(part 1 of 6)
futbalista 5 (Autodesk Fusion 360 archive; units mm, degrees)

design "futbalista 5" references "light sensor", "stlpik", "Raspberry Pi 4 Model B", "arduino nano strong", "futbalista 4", "18650 battery variations", "BTS7960 43A HIGH POWER H BRIDGE MODULE", "cam v2.1 rpi", "Solenoid JF-0826B"
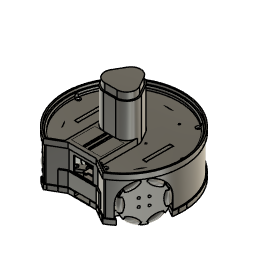
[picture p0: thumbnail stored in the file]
component_insert "Component Insert1"
step "00000000-0000-0000-0000-000000000000" TotalAngle 360
component_insert "Component Insert2"
component_insert "Component Insert3"
component_insert "Component Insert4"
component_insert "Component Insert5"
component_insert "Component Insert6"
component_insert "Component Insert7"
position "Position1"
component_insert "Component Insert8"
position "Position2"
component_insert "Component Insert9"
position "Position3"
sketch "Sketch1" plane through (0, 0, 0) normal (0, 0, 1) x axis (1, 0, 0)
  circle C1 centre (0, 0) radius 90
  circle C2 centre (0, 0) radius 86.5
  point P1 (0, 0)
  point P2 (0, 0)
  point P3 (0, 0)
  coincident P1 P2
  coincident P1 P3
component_insert "Component Insert11"
sketch "Sketch2" plane through (0, 0, -20.25) normal (0, 0, -1) x axis (1, 0, 0)
  line L1 (48.0762, -50.4536) -> (13.4352, -30.4536)
  line L2 (68.0762, -15.8125) -> (48.0762, -50.4536)
  line L3 (33.4352, 4.1875) -> (68.0762, -15.8125)
  line L4 (13.4352, -30.4536) -> (33.4352, 4.1875)
  line L5 (74.5, -6) -> (74.5, 6)
  line L6 (79.5, -6) -> (74.5, -6)
  line L7 (79.5, 6) -> (79.5, -6)
  line L8 (74.5, 6) -> (79.5, 6)
  circle C1 centre (46.9782, -46.3555) radius 1.5
  circle C2 centre (17.5333, -29.3555) radius 1.5
  circle C3 centre (34.5333, 0.0894) radius 1.5
  circle C4 centre (63.9782, -16.9106) radius 1.5
  circle C5 centre (77, 1) radius 1
position "Position8"
mirror_component "MirrorComponent1"
derived_instance "DerivedInstance1"
step "00000000-0000-0000-0000-000000000000" TotalAngle 360
component_insert "Component Insert12"
position "Position5"
position "Position9"
sketch "Sketch3" plane through (0, 0, -20.25) normal (0, 0, -1) x axis (1, 0, 0)
  line L1 (-71.6074, -10.2238) -> (-73.1099, -12.8262)
  line L2 (-73.1099, -7.1738) -> (-71.6074, -9.7762)
  line L3 (-76.5025, -6.95) -> (-73.4975, -6.95)
  line L4 (-78.3926, -9.7762) -> (-76.8901, -7.1738)
  line L5 (-76.8901, -12.8262) -> (-78.3926, -10.2238)
  line L6 (-73.4975, -13.05) -> (-76.5025, -13.05)
  arc A1 centre (-75, -10) radius 3.4 clockwise from (-71.6074, -9.7762) to (-71.6074, -10.2238)
  arc A2 centre (-75, -10) radius 3.4 clockwise from (-73.4975, -6.95) to (-73.1099, -7.1738)
  arc A3 centre (-75, -10) radius 3.4 clockwise from (-76.8901, -7.1738) to (-76.5025, -6.95)
  arc A4 centre (-75, -10) radius 3.4 clockwise from (-78.3926, -10.2238) to (-78.3926, -9.7762)
  arc A5 centre (-75, -10) radius 3.4 clockwise from (-76.5025, -13.05) to (-76.8901, -12.8262)
  arc A6 centre (-75, -10) radius 3.4 clockwise from (-73.1099, -12.8262) to (-73.4975, -13.05)
position "Position10"
mirror_component "MirrorComponent2"
derived_instance "DerivedInstance2"
step "00000000-0000-0000-0000-000000000000" TotalAngle 360
position "Position6"
position "Position7"
sketch "Sketch5" plane through (0, 0, -20.25) normal (0, 0, -1) x axis (1, 0, 0)
  line L1 (-18.5675, 22.4402) -> (-28.7175, 4.8598)
  line L2 (-43.0483, 40.0382) -> (-19.6656, 26.5382)
  line L3 (-56.1983, 17.2618) -> (-43.0483, 40.0382)
  line L4 (-32.8156, 3.7618) -> (-56.1983, 17.2618)
  line L5 (52.4064, -52.9536) -> (17.7653, -32.9536)
  line L6 (72.4064, -18.3125) -> (52.4064, -52.9536)
  line L7 (37.7653, 1.6875) -> (72.4064, -18.3125)
  line L8 (17.7653, -32.9536) -> (37.7653, 1.6875)
  line L9 (51.0414, -29.4688) -> (-36.6762, 21.175)
  line L10 (62.2343, -35.931) -> (51.0414, -29.4688)
  line L11 (26.9496, 67.1257) -> (25.4471, 69.7281)
  line L12 (30.3422, 66.9019) -> (27.3372, 66.9019)
  line L13 (32.2324, 69.7281) -> (30.7299, 67.1257)
  line L14 (30.7299, 72.7781) -> (32.2324, 70.1757)
  line L15 (27.3372, 73.0019) -> (30.3422, 73.0019)
  line L16 (25.4471, 70.1757) -> (26.9496, 72.7781)
  line L17 (-25.4471, 69.7281) -> (-26.9496, 67.1257)
  line L18 (-26.9496, 72.7781) -> (-25.4471, 70.1757)
  line L19 (-30.3422, 73.0019) -> (-27.3372, 73.0019)
  line L20 (-32.2324, 70.1757) -> (-30.7299, 72.7781)
  line L21 (-30.7299, 67.1257) -> (-32.2324, 69.7281)
  line L22 (-27.3372, 66.9019) -> (-30.3422, 66.9019)
  line L23 (28.8397, 69.9519) -> (-28.8397, 69.9519)
  line L24 (0, 0) -> (0, 69.9519)
  arc A1 centre (-31.3156, 6.3598) radius 3 clockwise from (-28.7175, 4.8598) to (-32.8156, 3.7618)
  arc A2 centre (-21.1656, 23.9402) radius 3 clockwise from (-19.6656, 26.5382) to (-18.5675, 22.4402)
  circle C1 centre (-34.6756, 10.8401) radius 1.7
  circle C2 centre (-36.6762, 21.175) radius 4.95
  circle C3 centre (-26.7256, 24.6099) radius 1.7
  circle C4 centre (-38.6768, 31.5099) radius 1.7
  circle C5 centre (-46.6268, 17.7401) radius 1.7
  circle C6 centre (51.3083, -48.8555) radius 1.5
  circle C7 centre (21.8634, -31.8555) radius 1.5
  circle C8 centre (38.8634, -2.4106) radius 1.5
  circle C9 centre (68.3083, -19.4106) radius 1.5
  arc A3 centre (28.8397, 69.9519) radius 3.4 clockwise from (27.3372, 66.9019) to (26.9496, 67.1257)
  arc A4 centre (28.8397, 69.9519) radius 3.4 clockwise from (30.7299, 67.1257) to (30.3422, 66.9019)
  arc A5 centre (28.8397, 69.9519) radius 3.4 clockwise from (32.2324, 70.1757) to (32.2324, 69.7281)
  arc A6 centre (28.8397, 69.9519) radius 3.4 clockwise from (30.3422, 73.0019) to (30.7299, 72.7781)
  arc A7 centre (28.8397, 69.9519) radius 3.4 clockwise from (26.9496, 72.7781) to (27.3372, 73.0019)
  arc A8 centre (28.8397, 69.9519) radius 3.4 clockwise from (25.4471, 69.7281) to (25.4471, 70.1757)
  arc A9 centre (-28.8397, 69.9519) radius 3.4 clockwise from (-25.4471, 70.1757) to (-25.4471, 69.7281)
  arc A10 centre (-28.8397, 69.9519) radius 3.4 clockwise from (-27.3372, 73.0019) to (-26.9496, 72.7781)
  arc A11 centre (-28.8397, 69.9519) radius 3.4 clockwise from (-30.7299, 72.7781) to (-30.3422, 73.0019)
  arc A12 centre (-28.8397, 69.9519) radius 3.4 clockwise from (-32.2324, 69.7281) to (-32.2324, 70.1757)
  arc A13 centre (-28.8397, 69.9519) radius 3.4 clockwise from (-30.3422, 66.9019) to (-30.7299, 67.1257)
  arc A14 centre (-28.8397, 69.9519) radius 3.4 clockwise from (-26.9496, 67.1257) to (-27.3372, 66.9019)
  point P11 (-36.6762, 21.175)
  point P23 (-36.6762, 21.175)
  point P25 (62.2343, -35.931)
  point P42 (-28.8397, 69.9519)
  point P52 (-28.8397, 69.9519)
  point P29 (28.8397, 69.9519)
  point P53 (28.8397, 69.9519)
  point P54 (0, 69.9519)
  point P1 (0, 0)
  point P55 (0, 0)
  coincident P11 P23
  perpendicular L8 L9
  coincident L6 P25
  perpendicular L6 L10
  coincident P42 P52
  coincident P29 P53
  midpoint L23 P54
  coincident P1 P55
position "Position11"
position "Position12"
position "Position13"
position "Position20"
position "Position22"
sketch "Sketch4" plane through (0, 0, -20.25) normal (0, 0, -1) x axis (1, 0, 0)
  line L1 (52.2343, -53.2515) -> (17.5933, -33.2515)
  line L2 (72.2343, -18.6105) -> (52.2343, -53.2515)
  line L3 (37.5933, 1.3895) -> (72.2343, -18.6105)
  line L4 (17.5933, -33.2515) -> (37.5933, 1.3895)
  line L5 (28.7175, 4.8598) -> (18.5675, 22.4402)
  line L6 (56.1983, 17.2618) -> (32.8156, 3.7618)
  line L7 (43.0483, 40.0382) -> (56.1983, 17.2618)
  line L8 (19.6656, 26.5382) -> (43.0483, 40.0382)
  line L9 (45.6463, 41.5382) -> (43.0483, 40.0382)
  line L10 (56.1983, 17.2618) -> (43.0483, 40.0382)
  line L11 (56.1983, 17.2618) -> (58.7963, 18.7618)
  line L12 (45.6463, 41.5382) -> (58.7963, 18.7618)
  line L13 (-18.5675, 22.4402) -> (-28.7175, 4.8598)
  line L14 (-43.0483, 40.0382) -> (-19.6656, 26.5382)
  line L15 (-56.1983, 17.2618) -> (-43.0483, 40.0382)
  line L16 (-32.8156, 3.7618) -> (-56.1983, 17.2618)
  line L17 (-58.7963, 18.7618) -> (-56.1983, 17.2618)
  line L18 (-43.0483, 40.0382) -> (-56.1983, 17.2618)
  line L19 (-43.0483, 40.0382) -> (-45.6463, 41.5382)
  line L20 (-58.7963, 18.7618) -> (-45.6463, 41.5382)
  line L21 (-10.15, -27.3) -> (10.15, -27.3)
  line L22 (-13.15, -57.3) -> (-13.15, -30.3)
  line L23 (13.15, -57.3) -> (-13.15, -57.3)
  line L24 (13.15, -30.3) -> (13.15, -57.3)
  line L25 (13.15, -60.3) -> (13.15, -57.3)
  line L26 (-13.15, -57.3) -> (13.15, -57.3)
  line L27 (-13.15, -57.3) -> (-13.15, -60.3)
  line L28 (13.15, -60.3) -> (-13.15, -60.3)
  line L29 (-42.4462, -61.5189) -> (-32.0538, -67.5189)
  line L30 (-44.9462, -65.849) -> (-42.4462, -61.5189)
  line L31 (-34.5538, -71.849) -> (-44.9462, -65.849)
  line L32 (-32.0538, -67.5189) -> (-34.5538, -71.849)
  line L33 (32.0538, -67.5189) -> (42.4462, -61.5189)
  line L34 (34.5538, -71.849) -> (32.0538, -67.5189)
  line L35 (44.9462, -65.849) -> (34.5538, -71.849)
  line L36 (42.4462, -61.5189) -> (44.9462, -65.849)
  line L37 (44.6578, -56.9019) -> (47.6628, -56.9019)
  line L38 (42.7676, -59.7281) -> (44.2701, -57.1257)
  line L39 (44.2701, -62.7781) -> (42.7676, -60.1757)
  line L40 (47.6628, -63.0019) -> (44.6578, -63.0019)
  line L41 (49.5529, -60.1757) -> (48.0504, -62.7781)
  line L42 (48.0504, -57.1257) -> (49.5529, -59.7281)
  line L43 (-47.6628, -56.9019) -> (-44.6578, -56.9019)
  line L44 (-49.5529, -59.7281) -> (-48.0504, -57.1257)
  line L45 (-48.0504, -62.7781) -> (-49.5529, -60.1757)
  line L46 (-44.6578, -63.0019) -> (-47.6628, -63.0019)
  line L47 (-42.7676, -60.1757) -> (-44.2701, -62.7781)
  line L48 (-44.2701, -57.1257) -> (-42.7676, -59.7281)
  line L49 (-71.6074, -10.2238) -> (-73.1099, -12.8262)
  line L50 (-73.1099, -7.1738) -> (-71.6074, -9.7762)
  line L51 (-76.5025, -6.95) -> (-73.4975, -6.95)
  line L52 (-78.3926, -9.7762) -> (-76.8901, -7.1738)
  line L53 (-76.8901, -12.8262) -> (-78.3926, -10.2238)
  line L54 (-73.4975, -13.05) -> (-76.5025, -13.05)
  line L55 (-74.5, 6) -> (-74.5, -6)
  line L56 (-79.5, 6) -> (-74.5, 6)
  line L57 (-79.5, -6) -> (-79.5, 6)
  line L58 (-74.5, -6) -> (-79.5, -6)
  line L59 (32.0538, 42.3849) -> (42.4462, 48.3849)
  line L60 (34.5538, 38.0548) -> (32.0538, 42.3849)
  line L61 (44.9462, 44.0548) -> (34.5538, 38.0548)
  line L62 (42.4462, 48.3849) -> (44.9462, 44.0548)
  line L63 (25.4471, 40.1757) -> (26.9496, 42.7781)
  line L64 (26.9496, 37.1257) -> (25.4471, 39.7281)
  line L65 (30.3422, 36.9019) -> (27.3372, 36.9019)
  line L66 (32.2324, 39.7281) -> (30.7299, 37.1257)
  line L67 (30.7299, 42.7781) -> (32.2324, 40.1757)
  line L68 (27.3372, 43.0019) -> (30.3422, 43.0019)
  line L69 (-26.9496, 42.7781) -> (-25.4471, 40.1757)
  line L70 (-30.3422, 43.0019) -> (-27.3372, 43.0019)
  line L71 (-32.2324, 40.1757) -> (-30.7299, 42.7781)
  line L72 (-30.7299, 37.1257) -> (-32.2324, 39.7281)
  line L73 (-27.3372, 36.9019) -> (-30.3422, 36.9019)
  line L74 (-25.4471, 39.7281) -> (-26.9496, 37.1257)
  line L75 (-42.4462, 48.3849) -> (-32.0538, 42.3849)
  line L76 (-44.9462, 44.0548) -> (-42.4462, 48.3849)
  line L77 (-34.5538, 38.0548) -> (-44.9462, 44.0548)
  line L78 (-32.0538, 42.3849) -> (-34.5538, 38.0548)
  line L79 (74.5, -6) -> (74.5, 6)
  line L80 (79.5, -6) -> (74.5, -6)
  line L81 (79.5, 6) -> (79.5, -6)
  line L82 (74.5, 6) -> (79.5, 6)
  line L83 (73.1099, -12.8262) -> (71.6074, -10.2238)
  line L84 (76.5025, -13.05) -> (73.4975, -13.05)
  line L85 (78.3926, -10.2238) -> (76.8901, -12.8262)
  line L86 (76.8901, -7.1738) -> (78.3926, -9.7762)
  line L87 (73.4975, -6.95) -> (76.5025, -6.95)
  line L88 (71.6074, -9.7762) -> (73.1099, -7.1738)
  line L89 (21.1244, -1.8038) -> (12.1244, -17.3923)
  line L90 (-9, 19.1962) -> (9, 19.1962)
  line L91 (-12.1244, -17.3923) -> (-21.1244, -1.8038)
  line L92 (74.5, 2.5) -> (79.5, 2.5)
  line L93 (74.5, -0.5) -> (79.5, -0.5)
  line L94 (-10.15, -27.3) -> (10.15, -27.3)
  line L95 (-13.15, -57.3) -> (-13.15, -30.3)
  line L96 (13.15, -57.3) -> (-13.15, -57.3)
  line L97 (13.15, -30.3) -> (13.15, -57.3)
  line L98 (-74.5, 2.5) -> (-79.5, 2.5)
  line L99 (-74.5, -0.5) -> (-79.5, -0.5)
  line L100 (28.8397, 54.9519) -> (-28.8397, 54.9519)
  line L101 (35.0849, -65.7689) -> (37.5849, -70.099)
  line L102 (37.683, -64.2689) -> (40.183, -68.599)
  line L103 (-37.683, -64.2689) -> (-40.183, -68.599)
  line L104 (-35.0849, -65.7689) -> (-37.5849, -70.099)
  line L105 (36.817, 45.1349) -> (39.317, 40.8048)
  line L106 (39.4151, 46.6349) -> (41.9151, 42.3048)
  line L107 (-36.817, 45.1349) -> (-39.317, 40.8048)
  line L108 (-39.4151, 46.6349) -> (-41.9151, 42.3048)
  line L109 (54.6936, 65.5371) -> (-54.6936, 65.5371)
  line L110 (-30, -81.1311) -> (-30, -65)
  line L111 (30, -65) -> (30, -81.1311)
  line L112 (-30, -65) -> (30, -65)
  line L113 (85.2616, 14.5848) -> (71.2917, 6.5192)
  line L114 (71.2917, 6.5192) -> (41.2917, 58.4808)
  line L115 (41.2917, 58.4808) -> (55.2616, 66.5463)
  line L116 (-55.2616, 66.5463) -> (-41.2917, 58.4808)
  line L117 (-41.2917, 58.4808) -> (-71.2917, 6.5192)
  line L118 (-71.2917, 6.5192) -> (-85.2616, 14.5848)
  line L119 (43.4208, 67.7929) -> (45.9208, 63.4628)
  line L120 (33.0285, 61.7929) -> (43.4208, 67.7929)
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  point P1 (0, 0)
  point P182 (0, 0)
  point P183 (0, 0)
  point P184 (0, 0)
  coincident P1 P182
  coincident P1 P183
  coincident P1 P184
  vertical L110
  parallel L110 L111
  perpendicular L110 L112
  dimension "d9" diameter = 3.4
  dimension "d10" diameter = 3.4
  dimension "d13" diameter = 3.4
  dimension "d14" diameter = 3.4
  dimension "d28" diameter = 3.4
  dimension "d148" diameter = 3.2
  dimension "d19" C-Pattern2-Angle = 360
position "Position14"
extrude "Extrude1" new body sketch "Sketch4" along normal blind 4
offset_faces "OffsetFaces5" distance -0.2
offset_faces "OffsetFaces6" distance -0.1
position "Position15"
position "Position18"
position "Position17"
position "Position16"
extrude "Extrude2" cut sketch "Sketch4" along normal blind 4 and along normal blind 2
extrude "Extrude3" add sketch "Sketch4" against normal blind 3
split "Split1"
split "Split2"
combine "Combine1"
sketch "Sketch6" plane through (74.5, 0, 0) normal (1, 0, 0) x axis (0, 1, 0)
  line L1 (0.5, -22.25) -> (0.5, -20.25)
  line L2 (-2.5, -22.25) -> (0.5, -22.25)
  line L3 (-2.5, -20.25) -> (-2.5, -22.25)
  line L4 (0.5, -20.25) -> (-2.5, -20.25)
  line L5 (6, -17.25) -> (6, -24.25)
  line L6 (-6, -24.25) -> (-6, -17.25)
  line L7 (6, -24.25) -> (-6, -24.25)
  line L8 (-6, -19.25) -> (6, -19.25)
  line L9 (-6, -20.25) -> (-6, -19.25)
  line L10 (6, -20.25) -> (-6, -20.25)
  line L11 (6, -19.25) -> (6, -20.25)
  line L12 (6.5, -19.75) -> (6, -19.25)
  line L13 (6, -20.25) -> (6.5, -19.75)
  line L14 (-6.5, -19.75) -> (-6, -19.25)
  line L15 (-6, -20.25) -> (-6.5, -19.75)
  line L16 (6, -22) -> (6.5, -21.5)
  line L17 (6.5, -21.5) -> (6, -21)
  line L18 (-6, -22) -> (-6.5, -21.5)
  line L19 (-6.5, -21.5) -> (-6, -21)
  line L20 (6, -23.75) -> (6.5, -23.25)
  line L21 (6.5, -23.25) -> (6, -22.75)
  line L22 (-6, -23.75) -> (-6.5, -23.25)
  line L23 (-6.5, -23.25) -> (-6, -22.75)
  line L24 (-6, -17.25) -> (6, -17.25)
  point P10 (6, -19.25)
  point P14 (6, -19.25)
  point P13 (6, -20.25)
  point P16 (6, -20.25)
  coincident P10 P14
  coincident P13 P16
  dimension "d40" R-Pattern1-uDistance = 0
  dimension "d41" R-Pattern1-vDistance = -3.5
extrude "Extrude4" cut sketch "Sketch6" profile of L5 L6 L9 L11 L12 L13 L14 L15 L16 L17 L18 L19 L20 L21 L22 L23 along normal blind 11.792
circular_pattern "C-Pattern1" TotalAngle 360
extrude "Extrude5" add sketch "Sketch6" profile of L5 L6 L9 L11 L12 L13 L14 L15 L16 L17 L18 L19 L20 L21 L22 L23 along normal blind 12 and along normal blind 5
extrude "Extrude6" cut sketch "Sketch4" against normal blind 3
cylinder_primitive "CylinderPrimitive1" Height -10 Diameter 173
combine "Combine2"
circular_pattern "C-Pattern2" TotalAngle 360
combine "Combine3"
offset_faces "OffsetFaces1" distance -0.2
circular_pattern "C-Pattern3" TotalAngle 360
extrude "Extrude7" cut of existing geometry blind -4.7
circular_pattern "C-Pattern4" TotalAngle 360
sketch "Sketch8" plane through (51.5285, -29.75, 0) normal (0.866, -0.5, 0) x axis (0.5, 0.866, 0)
  line L1 (-37, -24.25) -> (-37, -17.25)
  line L2 (-32, -24.25) -> (-37, -24.25)
  line L3 (-32, -17.25) -> (-32, -24.25)
  line L4 (-37, -19.25) -> (-32, -19.25)
  line L5 (-37, -20.25) -> (-37, -19.25)
  line L6 (-32, -20.25) -> (-37, -20.25)
  line L7 (-32, -19.25) -> (-32, -20.25)
  line L8 (-31.5, -19.75) -> (-32, -19.25)
  line L9 (-32, -20.25) -> (-31.5, -19.75)
  line L10 (-37.5, -19.75) -> (-37, -19.25)
  line L11 (-37, -20.25) -> (-37.5, -19.75)
  line L12 (-32, -22) -> (-31.5, -21.5)
  line L13 (-31.5, -21.5) -> (-32, -21)
  line L14 (-37.5, -21.5) -> (-37, -21)
  line L15 (-37, -22) -> (-37.5, -21.5)
  line L16 (-32, -23.75) -> (-31.5, -23.25)
  line L17 (-31.5, -23.25) -> (-32, -22.75)
  line L18 (-37.5, -23.25) -> (-37, -22.75)
  line L19 (-37, -23.75) -> (-37.5, -23.25)
  line L20 (-37, -17.25) -> (-32, -17.25)
  point P6 (-32, -19.25)
  point P10 (-32, -19.25)
  point P9 (-32, -20.25)
  point P12 (-32, -20.25)
  coincident P6 P10
  coincident P9 P12
  dimension "d65" R-Pattern1-uDistance = 0
  dimension "d66" R-Pattern1-vDistance = -3.5
extrude "Extrude8" new body sketch "Sketch8" profile of L1 L2 L3 L4 L5 L6 L7 L8 L9 L10 L11 L12 L13 L14 L15 L16 L17 L18 L19 along normal blind 22
combine "Combine4"
combine "Combine5"
extrude "Extrude9" cut of existing geometry blind -12
extrude "Extrude10" add sketch "Sketch8" profile of L1 L3 L12 L13 L14 L15 L16 L17 L18 L19 along normal blind 8.5
box_primitive "BoxPrimitive1" DistanceX 8 DistanceY 9 DistanceZ 25 OffsetDistanceX 0 OffsetDistanceY 0
combine "Combine6"
offset_faces "OffsetFaces2" distance -0.2
mirror "Mirror1" mirrorStitchTolerance 0.1
combine "Combine7"
extrude "Extrude11" cut of existing geometry blind -13
extrude "Extrude12" cut of existing geometry blind 37 second side blind 1.5
sketch "Sketch10" plane through (0, 0, -23.25) normal (0, 0, 1) x axis (-1, 0, 0)
  line L1 (-11, 23.2) -> (-11, 61.4086)
  line L2 (11, 23.2) -> (-11, 23.2)
  line L3 (11, 61.4086) -> (11, 23.2)
  curve K1 (-4.75, 30.7) -> (-6.5702, 29.2903)
  curve K2 (-7.4016, 30.1103) -> (-6, 31.95)
  line L4 (-6, 49.2) -> (-11, 49.2)
  line L5 (-6, 46.7) -> (-6, 49.2)
  line L6 (6, 46.7) -> (-6, 46.7)
  line L7 (6, 49.2) -> (6, 46.7)
  line L8 (11, 49.2) -> (6, 49.2)
  line L9 (11, 24.7) -> (11, 49.2)
  line L10 (-11, 24.7) -> (11, 24.7)
  line L11 (-11, 49.2) -> (-11, 24.7)
  curve K3 (5.4298, 42.7903) -> (7.25, 44.2)
  curve K4 (6, 45.45) -> (4.5984, 43.6103)
  line L12 (-11, 61.4086) -> (11, 61.4086)
  arc A1 centre (-6, 30.7) radius 1.5206 clockwise from (-6.5702, 29.2903) to (-7.4016, 30.1103)
  arc A2 centre (-6, 30.7) radius 1.25 clockwise from (-6, 31.95) to (-4.75, 30.7)
  arc A3 centre (6, 44.2) radius 1.25 clockwise from (6, 45.45) to (7.25, 44.2)
  arc A4 centre (6, 44.2) radius 1.5206 clockwise from (5.4298, 42.7903) to (4.5984, 43.6103)
  circle C1 centre (6, 44.2) radius 1.7
  circle C2 centre (-6, 30.7) radius 1.7
  concentric A3 C1
  concentric A1 C2
  dimension "d87" diameter C1 = 3.4
  dimension "d88" diameter C2 = 3.4
extrude "Extrude13" cut sketch "Sketch10" profile of A1 K1 A2 K2 K3 A3 K4 A4 C1 C2 against normal blind 1
fillet "Fillet1" radius 1.5
sketch "Sketch11" plane through (0, 0, -22.25) normal (0, 0, -1) x axis (1, 0, 0)
  line L1 (-40.2917, 60.2128) -> (-42.8897, 61.7128)
  line L2 (-37.7917, 64.5429) -> (-40.2917, 60.2128)
  line L3 (-40.3897, 66.0429) -> (-37.7917, 64.5429)
  line L4 (-42.8897, 61.7128) -> (-40.3897, 66.0429)
  line L5 (40.3897, 66.0429) -> (42.8897, 61.7128)
  line L6 (37.7917, 64.5429) -> (40.3897, 66.0429)
  line L7 (40.2917, 60.2128) -> (37.7917, 64.5429)
  line L8 (42.8897, 61.7128) -> (40.2917, 60.2128)
  line L9 (37.683, -64.2689) -> (40.183, -68.599)
  line L10 (35.0849, -65.7689) -> (37.683, -64.2689)
  line L11 (37.5849, -70.099) -> (35.0849, -65.7689)
  line L12 (-35.0849, -65.7689) -> (-37.5849, -70.099)
  line L13 (-37.683, -64.2689) -> (-35.0849, -65.7689)
  line L14 (-40.183, -68.599) -> (-37.683, -64.2689)
  line L15 (-74.5, 0) -> (-79.5, 0)
  line L16 (74.5, 0) -> (79.5, 0)
  line L17 (-74.5, 0) -> (-79.5, 0)
  line L18 (74.5, 0) -> (79.5, 0)
  line L19 (-37.25, -64.5189) -> (-39.75, -68.849)
  line L20 (37.25, -64.5189) -> (39.75, -68.849)
  line L21 (40.7247, 60.4628) -> (38.2247, 64.7929)
  line L22 (-40.7247, 60.4628) -> (-38.2247, 64.7929)
  line L23 (-79.5, -0.5) -> (-79.5, 2.5)
  line L24 (-74.5, -0.5) -> (-79.5, -0.5)
  line L25 (-74.5, 2.5) -> (-74.5, -0.5)
  line L26 (-79.5, 2.5) -> (-74.5, 2.5)
  line L27 (74.5, 2.5) -> (79.5, 2.5)
  line L28 (74.5, -0.5) -> (74.5, 2.5)
  line L29 (79.5, -0.5) -> (74.5, -0.5)
  line L30 (79.5, 2.5) -> (79.5, -0.5)
  line L31 (40.183, -68.599) -> (37.5849, -70.099)
  line L32 (-37.5849, -70.099) -> (-40.183, -68.599)
  point P30 (38.2247, 64.7929)
  point P31 (40.7247, 60.4628)
  point P32 (-38.2247, 64.7929)
  point P33 (-40.7247, 60.4628)
  point P8 (37.7917, 64.5429)
  point P4 (-37.7917, 64.5429)
  coincident L6 P30
  coincident L8 P31
  perpendicular L8 L21
  coincident L3 P32
  coincident L1 P33
  perpendicular L1 L22
  dimension "d95" distance P8 P30 = 0.5
  dimension "d96" distance P4 P32 = 0.5
  dimension "d94" C-Pattern1-Angle = 360
extrude "Extrude14" add sketch "Sketch11" profile of L1 L2 L3 L6 L7 L8 L9 L10 L13 L14 L15 L16 L17 L18 L19 L20 L21 L22 L23 L24 L25 L28 L29 L30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 along normal blind 2
sketch "Sketch12" plane through (0, 0, -20.25) normal (0, 0, 1) x axis (-1, 0, 0)
  line L1 (-13.15, -60.3) -> (13.15, -60.3)
  line L2 (13.15, -57.3) -> (13.15, -60.3)
  line L3 (-13.15, -57.3) -> (13.15, -57.3)
  line L4 (-13.15, -60.3) -> (-13.15, -57.3)
  line L5 (19.6656, 26.5382) -> (49.7167, 43.8882)
  line L6 (62.8667, 21.1118) -> (32.8156, 3.7618)
  line L7 (28.7175, 4.8598) -> (18.5675, 22.4402)
  line L8 (58.7963, 18.7618) -> (45.6463, 41.5382)
  line L9 (58.7963, 18.7618) -> (56.1983, 17.2618)
  line L10 (43.0483, 40.0382) -> (45.6463, 41.5382)
  line L11 (56.1983, 17.2618) -> (43.0483, 40.0382)
  line L12 (49.7167, 43.8882) -> (62.8667, 21.1118)
  line L13 (-32.8156, 3.7618) -> (-62.8667, 21.1118)
  line L14 (-49.7167, 43.8882) -> (-19.6656, 26.5382)
  line L15 (-18.5675, 22.4402) -> (-28.7175, 4.8598)
  line L16 (-45.6463, 41.5382) -> (-58.7963, 18.7618)
  line L17 (-45.6463, 41.5382) -> (-43.0483, 40.0382)
  line L18 (-56.1983, 17.2618) -> (-58.7963, 18.7618)
  line L19 (-43.0483, 40.0382) -> (-56.1983, 17.2618)
  line L20 (-62.8667, 21.1118) -> (-49.7167, 43.8882)
  line L21 (13.15, -65) -> (-13.15, -65)
  line L22 (13.15, -30.3) -> (13.15, -65)
  line L23 (-10.15, -27.3) -> (10.15, -27.3)
  line L24 (-13.15, -65) -> (-13.15, -30.3)
  circle C1 centre (7.95, -35.45) radius 1.7
  circle C2 centre (-7.95, -49.25) radius 1.7
  circle C3 centre (-7.95, -35.45) radius 1.7
  circle C4 centre (7.95, -49.25) radius 1.7
  circle C5 centre (46.6268, 17.7401) radius 1.7
  arc A1 centre (21.1656, 23.9402) radius 3 clockwise from (18.5675, 22.4402) to (19.6656, 26.5382)
  circle C6 centre (26.7256, 24.6099) radius 1.7
  circle C7 centre (34.6756, 10.8401) radius 1.7
  circle C8 centre (38.6768, 31.5099) radius 1.7
  arc A2 centre (31.3156, 6.3598) radius 3 clockwise from (32.8156, 3.7618) to (28.7175, 4.8598)
  circle C9 centre (-38.6768, 31.5099) radius 1.7
  arc A3 centre (-31.3156, 6.3598) radius 3 clockwise from (-28.7175, 4.8598) to (-32.8156, 3.7618)
  circle C10 centre (-34.6756, 10.8401) radius 1.7
  circle C11 centre (-26.7256, 24.6099) radius 1.7
  circle C12 centre (-46.6268, 17.7401) radius 1.7
  arc A4 centre (-21.1656, 23.9402) radius 3 clockwise from (-19.6656, 26.5382) to (-18.5675, 22.4402)
  arc A5 centre (10.15, -30.3) radius 3 clockwise from (10.15, -27.3) to (13.15, -30.3)
  arc A6 centre (-10.15, -30.3) radius 3 clockwise from (-13.15, -30.3) to (-10.15, -27.3)
extrude "Extrude15" cut sketch "Sketch12" profile of L1 L5 L6 L8 L12 L13 L14 L16 L20 L21 L22 L24 against normal blind 4
chamfer "Chamfer1" distance 2
chamfer "Chamfer2" distance 1
copy_paste_bodies "CopyPasteBodies1"
extrude "Extrude16" add sketch "Sketch8" profile of L1 L3 L5 L7 L8 L9 L10 L11 L12 L13 L14 L15 L16 L17 L18 L19 along normal blind 21.5
extrude "Extrude18" add of existing geometry blind 21.5 second side blind -12
cylinder_primitive "CylinderPrimitive2" Height -7 Diameter 173
extrude "Extrude17" cut sketch "Sketch4" against normal blind 3
box_primitive "BoxPrimitive2" DistanceX 7 DistanceY 28.779 DistanceZ 25 OffsetDistanceX 0 OffsetDistanceY 0
combine "Combine8"
mirror "Mirror2" mirrorStitchTolerance 0.1
combine "Combine9"
sketch "Sketch16" plane through (16, -27.7128, 0) normal (0.5, -0.866, 0) x axis (0.866, 0.5, 0)
  line L1 (-65.5, -22.25) -> (-65.5, -24.25)
  line L2 (-68, -22.25) -> (-65.5, -22.25)
  line L3 (-68, -20.25) -> (-68, -22.25)
  line L4 (-72, -19.75) -> (-71.5, -19.25)
  line L5 (-71.5, -20.25) -> (-72, -19.75)
  line L6 (-59, -19.75) -> (-59.5, -20.25)
  line L7 (-59.5, -19.25) -> (-59, -19.75)
  line L8 (-59, -21.5) -> (-59.5, -22)
  line L9 (-59.5, -21) -> (-59, -21.5)
  line L10 (-71.5, -22) -> (-72, -21.5)
  line L11 (-72, -21.5) -> (-71.5, -21)
  line L12 (-59, -23.25) -> (-59.5, -23.75)
  line L13 (-59.5, -22.75) -> (-59, -23.25)
  line L14 (-71.5, -23.75) -> (-72, -23.25)
  line L15 (-72, -23.25) -> (-71.5, -22.75)
  line L16 (-65, -24.25) -> (-65.5, -24.25)
  line L17 (-65.5, -24.25) -> (-71.5, -24.25)
  line L18 (-71.5, -24.25) -> (-71.5, -17.25)
  line L19 (-65, -20.25) -> (-68, -20.25)
  line L20 (-65, -24.25) -> (-65, -20.25)
  line L21 (-59.5, -17.25) -> (-59.5, -24.25)
  line L22 (-71.5, -17.25) -> (-59.5, -17.25)
  line L23 (-59.5, -24.25) -> (-65, -24.25)
  point P2 (-65.5, -24.25)
  point P24 (-65.5, -24.25)
  perpendicular L4 L5
  perpendicular L5 L6
  perpendicular L6 L7
  coincident P2 P24
  dimension "d129" R-Pattern1-uDistance = 0
  dimension "d130" R-Pattern1-vDistance = -3.5
extrude "Extrude19" cut sketch "Sketch16" profile of L1 L2 L3 L4 L5 L6 L7 L8 L9 L10 L11 L12 L13 L14 L15 L16 along normal blind 10.9 and along normal blind 5
extrude "Extrude20" cut of existing geometry blind -5
mirror "Mirror3" mirrorStitchTolerance 0.1
extrude "Extrude21" new body sketch "Sketch16" profile of L1 L2 L3 L4 L5 L6 L7 L8 L9 L10 L11 L12 L13 L14 L15 L16 along normal blind 10.9 and along normal blind 5
extrude "Extrude22" cut sketch "Sketch4" against normal blind 3
offset_faces "OffsetFaces4" distance -0.2
mirror "Mirror4" mirrorStitchTolerance 0.1
offset_faces "OffsetFaces7" distance -0.2
cylinder_primitive "CylinderPrimitive3" Height -7 Diameter 7.4
combine "Combine10"
mirror "Mirror5" mirrorStitchTolerance 0.1
circular_pattern "C-Pattern5" TotalAngle 360
combine "Combine13"
move "Move3"
move "Move4"
move "Move5"
move "Move6"
move "Move7"
move "Move8"
move "Move9"
move "Move10"
move "Move11"
move "Move12"
combine "Combine14"
move "Move13"
move "Move14"
combine "Combine15"
move "Move1"
position "Position21"
move "Move15"
move "Move17"
combine "Combine16"
extrude "Extrude23" cut of existing geometry blind 10.9
extrude "Extrude24" cut of existing geometry blind 10.9
position "Position23"
sketch "Sketch19" plane through (0, 0, 22.76) normal (0, 0, 1) x axis (-1, 0, 0)
  line L1 (-49.5, 0.3) -> (29.5, 0.3)
  line L2 (-52.5, -52.7) -> (-52.5, -2.7)
  line L3 (29.5, -55.7) -> (-49.5, -55.7)
  line L4 (32.5, -2.7) -> (32.5, -52.7)
  line L5 (-12.1244, -17.3923) -> (-21.1244, -1.8038)
  line L6 (21.1244, -1.8038) -> (12.1244, -17.3923)
  line L7 (-9, 19.1962) -> (9, 19.1962)
  line L8 (14, 39.3) -> (14, 36.5)
  line L9 (-14, 39.3) -> (14, 39.3)
  line L10 (-14, 36.5) -> (-14, 39.3)
  line L11 (14, 36.5) -> (-14, 36.5)
  line L12 (-32.0285, 63.525) -> (-42.4208, 69.525)
  line L13 (20.5628, 61.4086) -> (42.0987, 73.8424)
  line L14 (-41.2208, 71.6035) -> (-43.5906, 72.9716)
  line L15 (11.2, 57.5086) -> (21.6078, 57.5086)
  line L16 (-21.6078, 57.5086) -> (-11.2, 57.5086)
  line L17 (-43.5581, 70.1816) -> (-42.4208, 69.525)
  line L18 (20.9647, 59.9086) -> (30.8285, 65.6035)
  line L19 (11.2, 59.9086) -> (20.9647, 59.9086)
  line L20 (21.6078, 57.5086) -> (11.2, 57.5086)
  line L21 (32.0285, 63.525) -> (21.6078, 57.5086)
  line L22 (41.2208, 71.6035) -> (43.5906, 72.9716)
  line L23 (-21.6078, 57.5086) -> (-32.0285, 63.525)
  line L24 (-11.2, 57.5086) -> (-21.6078, 57.5086)
  line L25 (-20.9647, 59.9086) -> (-11.2, 59.9086)
  line L26 (-30.8285, 65.6035) -> (-20.9647, 59.9086)
  line L27 (-43.5906, 72.9716) -> (-41.2208, 71.6035)
  line L28 (-50.3778, 65.4587) -> (-52.6208, 66.7537)
  line L29 (81.8778, 10.8991) -> (84.1208, 12.1941)
  line L30 (31.5, -78.9478) -> (31.5, -76.3578)
  line L31 (-31.5, -76.3578) -> (-31.5, -78.9478)
  line L32 (-84.1208, 12.1941) -> (-81.8778, 10.8991)
  line L33 (-35.5285, 57.4628) -> (-32.0285, 63.525)
  line L34 (43.5581, 70.1816) -> (42.4208, 69.525)
  line L35 (52.6208, 66.7537) -> (50.3778, 65.4587)
  line L36 (-42.4208, 69.525) -> (-43.5581, 70.1816)
  line L37 (-32.0285, 63.525) -> (-21.6078, 57.5086)
  line L38 (42.4208, 69.525) -> (32.0285, 63.525)
  line L39 (30.8285, 65.6035) -> (41.2208, 71.6035)
  line L40 (-11.2, 57.5086) -> (11.2, 57.5086)
  line L41 (11.2, 59.9086) -> (-11.2, 59.9086)
  line L42 (-41.2208, 71.6035) -> (-30.8285, 65.6035)
  line L43 (-20.5628, 61.4086) -> (20.5628, 61.4086)
  line L44 (-42.0987, 73.8424) -> (-20.5628, 61.4086)
  line L45 (-43.5991, 74.7086) -> (-42.0987, 73.8424)
  line L46 (43.5991, 74.7086) -> (42.0987, 73.8424)
  line L47 (14, 61.4086) -> (14, 39.3)
  line L48 (-14, 61.4086) -> (-14, 39.3)
  line L49 (78.5484, -13.25) -> (75.4516, -13.25)
  line L50 (80.5888, -10.2841) -> (79.0404, -12.9659)
  line L51 (79.0404, -7.0341) -> (80.5888, -9.7159)
  line L52 (75.4516, -6.75) -> (78.5484, -6.75)
  line L53 (73.4112, -9.7159) -> (74.9596, -7.0341)
  line L54 (74.9596, -12.9659) -> (73.4112, -10.2841)
  line L55 (49.2006, -58.718) -> (50.749, -61.3999)
  line L56 (45.6119, -58.434) -> (48.7086, -58.434)
  line L57 (43.5715, -61.3999) -> (45.1199, -58.718)
  line L58 (45.1199, -64.6499) -> (43.5715, -61.968)
  line L59 (48.7086, -64.934) -> (45.6119, -64.934)
  line L60 (50.749, -61.968) -> (49.2006, -64.6499)
  line L61 (-50.749, -61.3999) -> (-49.2006, -58.718)
  line L62 (-49.2006, -64.6499) -> (-50.749, -61.968)
  line L63 (-45.6119, -64.934) -> (-48.7086, -64.934)
  line L64 (-43.5715, -61.968) -> (-45.1199, -64.6499)
  line L65 (-45.1199, -58.718) -> (-43.5715, -61.3999)
  line L66 (-48.7086, -58.434) -> (-45.6119, -58.434)
  line L67 (-75.4516, -13.25) -> (-78.5484, -13.25)
  line L68 (-73.4112, -10.2841) -> (-74.9596, -12.9659)
  line L69 (-74.9596, -7.0341) -> (-73.4112, -9.7159)
  line L70 (-78.5484, -6.75) -> (-75.4516, -6.75)
  line L71 (-80.5888, -9.7159) -> (-79.0404, -7.0341)
  line L72 (-79.0404, -12.9659) -> (-80.5888, -10.2841)
  line L73 (-32.3628, 60.8779) -> (-29.266, 60.8779)
  line L74 (-34.4032, 57.9119) -> (-32.8548, 60.5938)
  line L75 (-32.8548, 54.6619) -> (-34.4032, 57.3438)
  line L76 (-29.266, 54.3779) -> (-32.3628, 54.3779)
  line L77 (-27.2256, 57.3438) -> (-28.774, 54.6619)
  line L78 (-28.774, 60.5938) -> (-27.2256, 57.9119)
  line L79 (29.266, 60.8779) -> (32.3628, 60.8779)
  line L80 (27.2256, 57.9119) -> (28.774, 60.5938)
  line L81 (28.774, 54.6619) -> (27.2256, 57.3438)
  line L82 (32.3628, 54.3779) -> (29.266, 54.3779)
  line L83 (34.4032, 57.3438) -> (32.8548, 54.6619)
  line L84 (32.8548, 60.5938) -> (34.4032, 57.9119)
  arc A1 centre (-49.5, -2.7) radius 3 clockwise from (-52.5, -2.7) to (-49.5, 0.3)
  arc A2 centre (-49.5, -52.7) radius 3 clockwise from (-49.5, -55.7) to (-52.5, -52.7)
  arc A3 centre (29.5, -52.7) radius 3 clockwise from (32.5, -52.7) to (29.5, -55.7)
  arc A4 centre (29.5, -2.7) radius 3 clockwise from (29.5, 0.3) to (32.5, -2.7)
  circle C1 centre (29, -52.2) radius 3
  circle C2 centre (-29, -52.2) radius 3
  circle C3 centre (-30.27, -10.61) radius 0.5
  circle C4 centre (-27.73, -10.61) radius 0.5
  circle C5 centre (19.05, -1.93) radius 0.5
  circle C6 centre (16.51, -1.93) radius 0.5
  circle C7 centre (13.97, -1.93) radius 0.5
  circle C8 centre (11.43, -1.93) radius 0.5
  circle C9 centre (8.89, -1.93) radius 0.5
  circle C10 centre (6.35, -1.93) radius 0.5
  circle C11 centre (3.81, -1.93) radius 0.5
  circle C12 centre (1.27, -1.93) radius 0.5
  circle C13 centre (-1.27, -1.93) radius 0.5
  circle C14 centre (-3.81, -1.93) radius 0.5
  circle C15 centre (-6.35, -1.93) radius 0.5
  circle C16 centre (-8.89, -1.93) radius 0.5
  circle C17 centre (-11.43, -1.93) radius 0.5
  circle C18 centre (-13.97, -1.93) radius 0.5
  circle C19 centre (-16.51, -1.93) radius 0.5
  circle C20 centre (-19.05, -1.93) radius 0.5
  circle C21 centre (-21.59, -1.93) radius 0.5
  circle C22 centre (-24.13, -1.93) radius 0.5
  circle C23 centre (24.13, -4.47) radius 0.5
  circle C24 centre (21.59, -4.47) radius 0.5
  circle C25 centre (19.05, -4.47) radius 0.5
  circle C26 centre (16.51, -4.47) radius 0.5
  circle C27 centre (13.97, -4.47) radius 0.5
  circle C28 centre (11.43, -4.47) radius 0.5
  circle C29 centre (8.89, -4.47) radius 0.5
  circle C30 centre (6.35, -4.47) radius 0.5
  circle C31 centre (3.81, -4.47) radius 0.5
  circle C32 centre (1.27, -4.47) radius 0.5
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  point P117 (32.0285, 63.525)
  point P154 (32.0285, 63.525)
  point P150 (42.4208, 69.525)
  point P155 (42.4208, 69.525)
  point P118 (41.2208, 71.6035)
  point P156 (41.2208, 71.6035)
  point P112 (30.8285, 65.6035)
  point P157 (30.8285, 65.6035)
  point P115 (11.2, 57.5086)
  point P158 (11.2, 57.5086)
  point P121 (-11.2, 57.5086)
  point P159 (-11.2, 57.5086)
  point P122 (-11.2, 59.9086)
  point P160 (-11.2, 59.9086)
  point P114 (11.2, 59.9086)
  point P161 (11.2, 59.9086)
  point P124 (-30.8285, 65.6035)
  point P162 (-30.8285, 65.6035)
  point P129 (-50.3778, 65.4587)
  point P165 (-50.3778, 65.4587)
  point P152 (50.3778, 65.4587)
  point P164 (50.3778, 65.4587)
  point P75 (14, 39.3)
  point P171 (14, 39.3)
  point P172 (14, 61.4086)
  point P76 (-14, 39.3)
  point P173 (-14, 39.3)
  point P174 (-14, 61.4086)
  coincident P117 P154
  coincident P150 P155
  coincident P118 P156
  coincident P112 P157
  coincident P115 P158
  coincident P121 P159
  coincident P122 P160
  coincident P114 P161
  coincident P124 P162
  coincident P129 P165
  coincident P152 P164
  horizontal L43
  parallel L42 L44
  parallel L27 L45
  parallel L13 L46
  coincident P75 P171
  coincident L43 P172
  perpendicular L43 L47
  coincident P76 P173
  coincident L43 P174
  perpendicular L43 L48
extrude "Extrude25" new body sketch "Sketch4" against normal blind 55
sketch "Sketch20" plane through (0, 0, 0) normal (0, 1, 0) x axis (1, 0, 0)
  line L1 (-84.8, 20.25) -> (84.8, 20.25)
  line L2 (31.5, 20.25) -> (31.5, 0)
  line L3 (-31.5, 20.25) -> (-31.5, 0)
  line L4 (-30.75, 20.25) -> (-30.75, 0)
  line L5 (30.75, 20.25) -> (30.75, 0)
  circle C1 centre (0, 0) radius 31.5
  circle C2 centre (0, 0) radius 30.75
  point P6 (31.5, 0)
  point P7 (31.5, 20.25)
  point P8 (-31.5, 0)
  point P9 (-31.5, 20.25)
  point P11 (-30.75, 0)
  point P12 (-30.75, 20.25)
  point P13 (30.75, 0)
  point P14 (30.75, 20.25)
  coincident C1 P6
  coincident L1 P7
  tangent C1 L2
  perpendicular L1 L2
  coincident C1 P8
  coincident L1 P9
  tangent C1 L3
  perpendicular L1 L3
  concentric C1 C2
  coincident C2 P11
  coincident L1 P12
  tangent C2 L4
  perpendicular L1 L4
  coincident C2 P13
  coincident L1 P14
  tangent C2 L5
  perpendicular L1 L5
  dimension "d197" diameter C2 = 61.5
sketch "Sketch21" plane through (0, -59.7086, 0) normal (0, -1, 0) x axis (1, 0, 0)
  line L1 (-20.9647, -20.24) -> (-20.9647, 34.76)
  line L2 (20.9647, -20.24) -> (-20.9647, -20.24)
  line L3 (20.9647, 34.76) -> (20.9647, -20.24)
  line L4 (-20.9647, 34.76) -> (20.9647, 34.76)
  line L5 (11.2, -23.25) -> (11.2, -17.25)
  line L6 (-11.2, -23.25) -> (11.2, -23.25)
  line L7 (-11.2, -17.25) -> (-11.2, -23.25)
  line L8 (-6, 1.75) -> (6, 1.75)
  line L9 (-11.2, 1.75) -> (-11.2, -17.25)
  line L10 (-6, 1.75) -> (-11.2, 1.75)
  line L11 (11.2, 1.75) -> (6, 1.75)
  line L12 (11.2, -17.25) -> (11.2, 1.75)
  line L13 (21.0183, -20.25) -> (-21.0183, -20.25)
  line L14 (21.0183, 34.75) -> (21.0183, -20.25)
  line L15 (-21.0183, 34.75) -> (21.0183, 34.75)
  line L16 (-21.0183, -20.25) -> (-21.0183, 34.75)
  point P9 (-11.2, -17.25)
  point P12 (-11.2, -17.25)
  point P11 (-6, 1.75)
  point P14 (-6, 1.75)
  point P10 (6, 1.75)
  point P15 (6, 1.75)
  point P6 (11.2, -17.25)
  point P17 (11.2, -17.25)
  coincident P9 P12
  perpendicular L8 L9
  coincident P11 P14
  perpendicular L7 L10
  coincident P10 P15
  perpendicular L5 L11
  coincident P6 P17
  perpendicular L8 L12
extrude "Extrude28" cut sketch "Sketch21" profile of L2 L5 L6 L7 L8 L9 L10 L11 L12 against normal blind 2.4
extrude "Extrude29" new body sketch "Sketch19" along normal blind 6.99 and along normal blind 3.99
sketch "Sketch22" plane through (0, 0, 29.75) normal (0, 0, 1) x axis (-1, 0, 0)
  line L1 (9, 19.1962) -> (-9, 19.1962)
  line L2 (12.1244, -17.3923) -> (21.1244, -1.8038)
  line L3 (-21.1244, -1.8038) -> (-12.1244, -17.3923)
  line L4 (-45.6119, -58.434) -> (-48.7086, -58.434)
  line L5 (-43.5715, -61.3999) -> (-45.1199, -58.718)
  line L6 (-45.1199, -64.6499) -> (-43.5715, -61.968)
  line L7 (-48.7086, -64.934) -> (-45.6119, -64.934)
  line L8 (-50.749, -61.968) -> (-49.2006, -64.6499)
  line L9 (-49.2006, -58.718) -> (-50.749, -61.3999)
  line L10 (49.2006, -64.6499) -> (50.749, -61.968)
  line L11 (45.6119, -64.934) -> (48.7086, -64.934)
  line L12 (43.5715, -61.968) -> (45.1199, -64.6499)
  line L13 (45.1199, -58.718) -> (43.5715, -61.3999)
  line L14 (48.7086, -58.434) -> (45.6119, -58.434)
  line L15 (50.749, -61.3999) -> (49.2006, -58.718)
  line L16 (34.4032, 57.9119) -> (32.8548, 60.5938)
  line L17 (32.8548, 54.6619) -> (34.4032, 57.3438)
  line L18 (29.266, 54.3779) -> (32.3628, 54.3779)
  line L19 (27.2256, 57.3438) -> (28.774, 54.6619)
  line L20 (28.774, 60.5938) -> (27.2256, 57.9119)
  line L21 (32.3628, 60.8779) -> (29.266, 60.8779)
  line L22 (-27.2256, 57.9119) -> (-28.774, 60.5938)
  line L23 (-28.774, 54.6619) -> (-27.2256, 57.3438)
  line L24 (-32.3628, 54.3779) -> (-29.266, 54.3779)
  line L25 (-34.4032, 57.3438) -> (-32.8548, 54.6619)
  line L26 (-32.8548, 60.5938) -> (-34.4032, 57.9119)
  line L27 (-29.266, 60.8779) -> (-32.3628, 60.8779)
  line L28 (-80.5888, -10.2841) -> (-79.0404, -12.9659)
  line L29 (-79.0404, -7.0341) -> (-80.5888, -9.7159)
  line L30 (-75.4516, -6.75) -> (-78.5484, -6.75)
  line L31 (-73.4112, -9.7159) -> (-74.9596, -7.0341)
  line L32 (-74.9596, -12.9659) -> (-73.4112, -10.2841)
  line L33 (-78.5484, -13.25) -> (-75.4516, -13.25)
  line L34 (73.4112, -10.2841) -> (74.9596, -12.9659)
  line L35 (74.9596, -7.0341) -> (73.4112, -9.7159)
  line L36 (78.5484, -6.75) -> (75.4516, -6.75)
  line L37 (80.5888, -9.7159) -> (79.0404, -7.0341)
  line L38 (79.0404, -12.9659) -> (80.5888, -10.2841)
  line L39 (75.4516, -13.25) -> (78.5484, -13.25)
  line L40 (21.6078, 57.5086) -> (43.5581, 70.1816)
  line L41 (-21.6078, 57.5086) -> (21.6078, 57.5086)
  line L42 (-32.0285, 63.525) -> (-21.6078, 57.5086)
  line L43 (-43.5581, 70.1816) -> (-32.0285, 63.525)
  line L44 (-20.5628, 61.4086) -> (20.5628, 61.4086)
  line L45 (-43.5991, 74.7086) -> (-20.5628, 61.4086)
  line L46 (20.5628, 61.4086) -> (43.5991, 74.7086)
  line L47 (20.9647, 59.9086) -> (-20.9647, 59.9086)
  line L48 (43.5906, 72.9716) -> (20.9647, 59.9086)
  line L49 (-41.2208, 71.6035) -> (-43.5906, 72.9716)
  line L50 (-20.9647, 59.9086) -> (-41.2208, 71.6035)
  arc A1 centre (-9, 5.1962) radius 14 clockwise from (-21.1244, -1.8038) to (-9, 19.1962)
  arc A2 centre (9, 5.1962) radius 14 clockwise from (9, 19.1962) to (21.1244, -1.8038)
  arc A3 centre (0, -10.3923) radius 14 clockwise from (12.1244, -17.3923) to (-12.1244, -17.3923)
  arc A4 centre (-47.1603, -61.684) radius 3.6 clockwise from (-49.2006, -58.718) to (-48.7086, -58.434)
  arc A5 centre (-47.1603, -61.684) radius 3.6 clockwise from (-45.6119, -58.434) to (-45.1199, -58.718)
  arc A6 centre (-47.1603, -61.684) radius 3.6 clockwise from (-43.5715, -61.3999) to (-43.5715, -61.968)
  arc A7 centre (-47.1603, -61.684) radius 3.6 clockwise from (-45.1199, -64.6499) to (-45.6119, -64.934)
  arc A8 centre (-47.1603, -61.684) radius 3.6 clockwise from (-48.7086, -64.934) to (-49.2006, -64.6499)
  arc A9 centre (-47.1603, -61.684) radius 3.6 clockwise from (-50.749, -61.968) to (-50.749, -61.3999)
  arc A10 centre (47.1603, -61.684) radius 3.6 clockwise from (50.749, -61.3999) to (50.749, -61.968)
  arc A11 centre (47.1603, -61.684) radius 3.6 clockwise from (49.2006, -64.6499) to (48.7086, -64.934)
  arc A12 centre (47.1603, -61.684) radius 3.6 clockwise from (45.6119, -64.934) to (45.1199, -64.6499)
  arc A13 centre (47.1603, -61.684) radius 3.6 clockwise from (43.5715, -61.968) to (43.5715, -61.3999)
  arc A14 centre (47.1603, -61.684) radius 3.6 clockwise from (45.1199, -58.718) to (45.6119, -58.434)
  arc A15 centre (47.1603, -61.684) radius 3.6 clockwise from (48.7086, -58.434) to (49.2006, -58.718)
  arc A16 centre (30.8144, 57.6279) radius 3.6 clockwise from (32.3628, 60.8779) to (32.8548, 60.5938)
  arc A17 centre (30.8144, 57.6279) radius 3.6 clockwise from (34.4032, 57.9119) to (34.4032, 57.3438)
  arc A18 centre (30.8144, 57.6279) radius 3.6 clockwise from (32.8548, 54.6619) to (32.3628, 54.3779)
  arc A19 centre (30.8144, 57.6279) radius 3.6 clockwise from (29.266, 54.3779) to (28.774, 54.6619)
  arc A20 centre (30.8144, 57.6279) radius 3.6 clockwise from (27.2256, 57.3438) to (27.2256, 57.9119)
  arc A21 centre (30.8144, 57.6279) radius 3.6 clockwise from (28.774, 60.5938) to (29.266, 60.8779)
  circle C1 centre (-29, -52.2) radius 1.35
  circle C2 centre (29, -52.2) radius 1.35
  circle C3 centre (29, -3.2) radius 1.35
  arc A22 centre (-30.8144, 57.6279) radius 3.6 clockwise from (-29.266, 60.8779) to (-28.774, 60.5938)
  arc A23 centre (-30.8144, 57.6279) radius 3.6 clockwise from (-27.2256, 57.9119) to (-27.2256, 57.3438)
  arc A24 centre (-30.8144, 57.6279) radius 3.6 clockwise from (-28.774, 54.6619) to (-29.266, 54.3779)
  arc A25 centre (-30.8144, 57.6279) radius 3.6 clockwise from (-32.3628, 54.3779) to (-32.8548, 54.6619)
  arc A26 centre (-30.8144, 57.6279) radius 3.6 clockwise from (-34.4032, 57.3438) to (-34.4032, 57.9119)
  arc A27 centre (-30.8144, 57.6279) radius 3.6 clockwise from (-32.8548, 60.5938) to (-32.3628, 60.8779)
  circle C4 centre (-29, -3.2) radius 1.35
  arc A28 centre (-77, -10) radius 3.6 clockwise from (-78.5484, -13.25) to (-79.0404, -12.9659)
  arc A29 centre (-77, -10) radius 3.6 clockwise from (-80.5888, -10.2841) to (-80.5888, -9.7159)
  arc A30 centre (-77, -10) radius 3.6 clockwise from (-79.0404, -7.0341) to (-78.5484, -6.75)
  arc A31 centre (-77, -10) radius 3.6 clockwise from (-75.4516, -6.75) to (-74.9596, -7.0341)
  arc A32 centre (-77, -10) radius 3.6 clockwise from (-73.4112, -9.7159) to (-73.4112, -10.2841)
  arc A33 centre (-77, -10) radius 3.6 clockwise from (-74.9596, -12.9659) to (-75.4516, -13.25)
  arc A34 centre (77, -10) radius 3.6 clockwise from (75.4516, -13.25) to (74.9596, -12.9659)
  arc A35 centre (77, -10) radius 3.6 clockwise from (73.4112, -10.2841) to (73.4112, -9.7159)
  arc A36 centre (77, -10) radius 3.6 clockwise from (74.9596, -7.0341) to (75.4516, -6.75)
  arc A37 centre (77, -10) radius 3.6 clockwise from (78.5484, -6.75) to (79.0404, -7.0341)
  arc A38 centre (77, -10) radius 3.6 clockwise from (80.5888, -9.7159) to (80.5888, -10.2841)
  arc A39 centre (77, -10) radius 3.6 clockwise from (79.0404, -12.9659) to (78.5484, -13.25)
  arc A40 centre (0, 0) radius 82.6 clockwise from (43.5581, 70.1816) to (-43.5581, 70.1816)
  arc A41 centre (0, 0) radius 86.5 clockwise from (43.5991, 74.7086) to (-43.5991, 74.7086)
  arc A42 centre (0, 0) radius 85 clockwise from (43.5906, 72.9716) to (-43.5906, 72.9716)
  circle C5 centre (-30.8144, 57.6279) radius 1.7
  circle C6 centre (30.8144, 57.6279) radius 1.7
  circle C7 centre (77, -10) radius 1.7
  circle C8 centre (47.1603, -61.684) radius 1.7
  circle C9 centre (-47.1603, -61.684) radius 1.7
  circle C10 centre (-77, -10) radius 1.7
extrude "Extrude31" add sketch "Sketch22" along normal blind 5
extrude "Extrude30" cut sketch "Sketch20" profile of C1 L1 L2 L3 along normal blind 90 and along normal blind 65
sketch "Sketch23" plane through (0, 0, 34.75) normal (0, 0, 1) x axis (-1, 0, 0)
  line L1 (12.1244, -17.3923) -> (21.1244, -1.8038)
  line L2 (-21.1244, -1.8038) -> (-12.1244, -17.3923)
  line L3 (9, 19.1962) -> (-9, 19.1962)
  line L4 (-43.5581, 70.1816) -> (-21.6078, 57.5086)
  line L5 (21.6078, 57.5086) -> (43.5581, 70.1816)
  line L6 (-21.6078, 57.5086) -> (21.6078, 57.5086)
  line L7 (-20.9647, 59.9086) -> (-43.5906, 72.9716)
  line L8 (20.9647, 59.9086) -> (-20.9647, 59.9086)
  line L9 (43.5906, 72.9716) -> (20.9647, 59.9086)
  line L10 (20.5628, 61.4086) -> (43.5991, 74.7086)
  line L11 (-20.5628, 61.4086) -> (20.5628, 61.4086)
  line L12 (-43.5991, 74.7086) -> (-20.5628, 61.4086)
  circle C1 centre (-30.8144, 57.6279) radius 1.7
  circle C2 centre (77, -10) radius 1.7
  circle C3 centre (30.8144, 57.6279) radius 1.7
  circle C4 centre (47.1603, -61.684) radius 1.7
  circle C5 centre (-29, -52.2) radius 1.35
  circle C6 centre (-77, -10) radius 1.7
  arc A1 centre (9, 5.1962) radius 14 clockwise from (9, 19.1962) to (21.1244, -1.8038)
  arc A2 centre (0, -10.3923) radius 14 clockwise from (12.1244, -17.3923) to (-12.1244, -17.3923)
  arc A3 centre (-9, 5.1962) radius 14 clockwise from (-21.1244, -1.8038) to (-9, 19.1962)
  circle C7 centre (29, -3.2) radius 1.35
  circle C8 centre (29, -52.2) radius 1.35
  circle C9 centre (-47.1603, -61.684) radius 1.7
  circle C10 centre (-29, -3.2) radius 1.35
  arc A4 centre (0, 0) radius 82.6 clockwise from (43.5581, 70.1816) to (-43.5581, 70.1816)
  arc A5 centre (0, 0) radius 85 clockwise from (43.5906, 72.9716) to (-43.5906, 72.9716)
  arc A6 centre (0, 0) radius 86.5 clockwise from (43.5991, 74.7086) to (-43.5991, 74.7086)
extrude "Extrude32" add sketch "Sketch23" along normal blind 6
circular_pattern "C-Pattern7" TotalAngle 360
extrude "Extrude33" cut sketch "Sketch23" profile of A5 L7 L8 L9 L10 L11 L12 A6 against normal blind 2 and against normal blind 8
sketch "Sketch24" plane through (14, 0, 0) normal (1, 0, 0) x axis (0, 1, 0)
  line L1 (-32.5, 8.25) -> (-32.5, 1.75)
  line L2 (-39.5, 1.75) -> (-39.5, 8.25)
  line L3 (-32.5, 1.75) -> (-39.5, 1.75)
  line L4 (-39.3, 38.75) -> (-36.5, 38.75)
  line L5 (-39.3, 11.75) -> (-39.3, 38.75)
  line L6 (-36.5, 11.75) -> (-39.3, 11.75)
  line L7 (-36.5, 38.75) -> (-36.5, 11.75)
  line L8 (-66.678, 8.25) -> (-36, 8.25)
  line L9 (-5.322, 8.25) -> (-36, 8.25)
  circle C1 centre (-36, 8.25) radius 1.7
  arc A1 centre (-36, 8.25) radius 3.5 clockwise from (-39.5, 8.25) to (-32.5, 8.25)
  circle C2 centre (-36, 8.25) radius 30.678
  point P8 (-39.3, 38.75)
  point P11 (-36, 8.25)
  point P12 (-36, 8.25)
  point P13 (-66.678, 8.25)
  point P14 (-36, 8.25)
  point P15 (-5.322, 8.25)
  concentric C1 C2
  coincident P8 C2
  coincident P11 P12
  coincident C2 P13
  perpendicular L2 L8
  coincident P11 P14
  coincident C2 P15
  perpendicular L1 L9
extrude "Extrude34" cut sketch "Sketch24" profile of A1 L4 L5 L6 L7 C2 L8 L9 against normal blind 28
offset_faces "OffsetFaces8" distance -0.2
shell "Shell1" innerThickness 2
extrude "Extrude35" cut of existing geometry blind -12
extrude "Extrude36" cut of existing geometry blind -9.0025
chamfer "Chamfer3" distance 1.5
extrude "Extrude37" add of existing geometry blind 50
offset_faces "OffsetFaces10" distance -0.2
split "Split3"
fillet "Fillet2" radius 0.8
fillet "Fillet3" radius 2
combine "Combine19"
extrude "Extrude38" add of existing geometry blind 28.4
